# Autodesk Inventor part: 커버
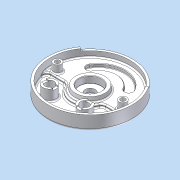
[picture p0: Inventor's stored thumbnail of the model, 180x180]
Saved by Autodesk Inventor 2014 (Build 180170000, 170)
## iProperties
Company: 한국ATC센터
Created: 2015-04
Part Number: 커버
Document SubType Name: Modeling
Designer: KYOUNG IL JANG
Density: 1 g/cm^3
Material: 일반
Mass: 394.015 g
Surface Area: 1019.6 cm^2
Volume: 394.015 cm^3
Appearance: 매끄러움 - 흰색
Author: KYOUNG IL JANG
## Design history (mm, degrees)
sketch "스케치1"
  geometry: L1 (-59, -19)-(-59, 19); L2 (59, 19)-(59, -19); L3 (-41, 19)-(-41, -19); L4 (41, -19)-(41, 19); L5 (38.527, 33.023)-(55.442, 39.179); L6 (-38.527, 33.023)-(-55.442, 39.179); C1 r 90 at (0, 0); C2 r 95 at (0, 0); A1 r 59 centre (0, 19) between (59, 19) and (-59, 19); A2 r 59 centre (0, -19) between (-59, -19) and (59, -19); A3 r 41 centre (0, -19) between (-41, -19) and (41, -19); A4 r 41 centre (0, 19) between (41, 19) and (-41, 19); 2 further points
  constraints: 12 end point, 12 point on circle, 6 centre point, 4 tangent, 2 parallel, 2 point on line, 1 coincident, 1 horizontal alignment, 1 midpoint, 1 vertical, 1 vertical alignment, 3 other
  dimensions: "d2" = 180 diameter of C1; "d3" = 156 dimension on A2 A1; "d4" = 118 distance between parallel lines of L2 L1; "d5" = 18 distance between parallel lines of L2 L4; "d8" = 190 diameter of C2; "d120" = 140 deg angle of L6 L5; "d121" = 110 deg dimension on A1.centre point (0, 0) L5.end
extrude "돌출1" new body sketch "스케치1" distance "d6" = 14; taper "d7" = 0 deg
extrude "돌출2" join sketch "스케치1" distance "d9" = 13; taper "d10" = 0 deg
extrude "돌출3" cut sketch "스케치1" distance "d11" = 7; taper "d12" = 0 deg
sketch "스케치2"
  geometry: C1 r 11.5 at (0, 0); 1 further point
  constraints: 1 centre point, 1 coincident
  dimensions: "d13" = 23 diameter of C1
extrude "돌출4" cut sketch "스케치2" stored distance "d14" = 7; taper "d15" = 0 deg
fillet "모깎기1"
fillet "모깎기2"
sketch "스케치3"
  geometry: L1 (-73.724, 51.622)-(-77.819, 54.49); L2 (73.724, 51.622)-(77.819, 54.49); L3 (0, 0)-(0, -90); A1 r 95 centre (0, 0) between (-77.819, 54.49) and (77.819, 54.49) reference; A2 r 90 centre (0, 0) between (-73.724, 51.622) and (73.724, 51.622) reference; 1 further point
  constraints: 6 end point, 5 point on circle, 1 point on line, 1 vertical, 1 other
  dimensions: "d16" = 250 deg dimension on L2 L1
extrude "돌출5" join sketch "스케치3" distance "d17" = 5; taper "d18" = 0 deg
hole "구멍1" diameter "d21" = 50; stored, may be unused: countersink angle "d25" = 90 deg, drill point angle "d27" = 0 deg; dims "d19" = 10, "d20" = 10, "d22" = 6, "d23" = 4, "d24" = 2, "d26" = 5
fillet "모깎기3" dims "d28" = 0.3
fillet "모깎기5" dims "d30" = 3
sketch "스케치4"
  geometry: C1 r 35 at (0, 0); C2 r 25 at (0, 0); 1 further point
  constraints: 2 centre point, 1 coincident
  dimensions: "d32" = 70 diameter of C1 (derived); "d36" = 10 radial gap between concentric circles of C1 C2
extrude "돌출6" join sketch "스케치4" distance "d33" = 10; taper "d34" = 0 deg
feature "면 기울기2" dims angle "d37" = 10 deg
chamfer "모따기1" distance "d39" = 1; stored, may be unused: second distance "d40" = 2, angle "d41" = 45 deg
fillet "모깎기7" dims "d42" = 5
sketch "스케치5"
  geometry: L1 (-40.249, -12)-(-89.196, -12); L2 (40.249, -12)-(89.196, -12); A1 r 90 centre (0, 0) between (-89.196, -12) and (89.196, -12) reference; A2 r 42 centre (0, 0) between (-40.249, -12) and (40.249, -12); 1 further point
  constraints: 4 end point, 4 point on circle, 1 centre point, 1 collinear, 1 horizontal, 1 point on line
  dimensions: "d43" = 48 radial gap between concentric circles of A1 A2; "d44" = 12 distance from line of point (0, 0) L1
extrude "돌출7" cut sketch "스케치5" stored distance "d45" = 10; taper "d46" = 0 deg
fillet "모깎기8" dims "d47" = 10
chamfer "모따기2" distance "d49" = 1; stored, may be unused: second distance "d50" = 2, angle "d51" = 45 deg
sketch "스케치7"
  geometry: L1 (36.062, 36.062)-(50.912, 50.912); L2 (-36.062, 36.062)-(-50.912, 50.912); A1 r 72 centre (0, 0) between (50.912, 50.912) and (-50.912, 50.912); A2 r 51 centre (0, 0) between (36.062, 36.062) and (-36.062, 36.062); 1 further point
  constraints: 8 point on circle, 4 end point, 2 centre point, 2 point on line, 1 coincident, 1 horizontal alignment
  dimensions: "d54" = 72 radius of A1; "d55" = 21 radial gap between concentric circles of A1 A2; "d56" = 90 deg angle of L2 L1
extrude "돌출8" join sketch "스케치7" distance "d57" = 5; taper "d58" = 0 deg
fillet "모깎기10" dims "d59" = 5
fillet "모깎기11" dims "d60" = 5
fillet "모깎기12" dims "d61" = 3
sketch "스케치6"
  geometry: C1 r 68 at (0, 0); 1 further point
  constraints: 1 centre point, 1 other
  dimensions: "d119" = 136 diameter of C1
feature "엠보싱1" sketch "스케치6" dims "d62" = 0.5, "d63" = 0
sketch "스케치8"
  geometry: C1 r 9 at (74, 0); C2 r 9 at (-74, 0); A1 r 74 centre (0, 0) between (74, 0) and (-74, 0); 1 further point
  constraints: 3 centre point, 2 horizontal alignment, 2 point on circle, 1 coincident, 1 equal radius
  dimensions: "d64" = 18 diameter of C1; "d65" = 148 diameter of A1
extrude "돌출9" join sketch "스케치8" stored distance "d66" = 5; taper "d67" = 0 deg
sketch "스케치11"
  geometry: C1 r 15 at (40, -52); C2 r 15 at (-40, -52); 1 further point
  constraints: 2 centre point, 1 equal radius, 1 horizontal alignment
  dimensions: "d83" = 52 vertical distance of point (0, 0) C1.centre; "d84" = 80 distance of C2.centre C1.centre; "d85" = 40 horizontal distance of point (0, 0) C1.centre (= 0.5 x d84); "d86" = 30 diameter of C1
extrude "돌출10" join sketch "스케치11" stored distance "d87" = 5; taper "d88" = 0 deg
node "구멍3"
node "구멍5"
hole "구멍6" diameter "d93" = 20; stored, may be unused: countersink angle "d97" = 90 deg, drill point angle "d99" = 118 deg; dims "d91" = 10, "d92" = 10, "d94" = 6, "d95" = 4, "d96" = 2, "d98" = 8
hole "구멍7" diameter "d102" = 20; stored, may be unused: countersink angle "d106" = 90 deg, drill point angle "d108" = 118 deg; dims "d100" = 10, "d101" = 10, "d103" = 6, "d104" = 4, "d105" = 2, "d107" = 8
sketch "스케치13"
  geometry: L1 (6, -13.748)-(6, -8); L2 (6, 8)-(6, 13.748); L3 (-6, -13.748)-(-6, -8); L4 (-6, 8)-(-6, 13.748); L5 (-66.252, -6)-(-72, -6); L6 (-88, -6)-(-93.748, -6); L7 (-66.252, 6)-(-72, 6); L8 (-88, 6)-(-93.748, 6); A1 r 15 centre (0, 0) between (6, -13.748) and (6, 13.748) reference; A2 r 10 centre (0, 0) between (6, -8) and (6, 8) reference; A3 r 15 centre (-80, 0) between (-66.252, -6) and (-93.748, -6) reference; A4 r 10 centre (-80, 0) between (-72, -6) and (-88, -6) reference; 1 further point
  constraints: 16 end point, 16 point on circle, 4 equal length, 3 collinear, 2 point on line, 1 perpendicular, 1 vertical
  dimensions: "d109" = 12 distance between parallel lines of L3 L1; "d110" = 6 distance from line of A1.centre L1 (= 0.5 x d109); "d111" = 12 distance between parallel lines of L7 L5; "d112" = 6 distance from line of A3.centre L5 (= 0.5 x d111)
extrude "돌출12" cut sketch "스케치13" distance "d113" = 3; taper "d114" = 0 deg
fillet "모깎기13" dims "d115" = 3
fillet "모깎기14" dims "d116" = 1
node "솔리드1"
sketch "스케치9"
  geometry: 1 further point
hole "구멍2" sketch "스케치9" diameter "d68" = 11; stored, may be unused: countersink angle "d72" = 90 deg, drill point angle "d74" = 0 deg; dims "d69" = 6, "d70" = 18, "d71" = 11, "d73" = 8
sketch "스케치10"
  geometry: 1 further point
hole "구멍4" sketch "스케치10" diameter "d75" = 11; stored, may be unused: countersink angle "d79" = 90 deg, drill point angle "d81" = 0 deg; dims "d76" = 6, "d77" = 18, "d78" = 11, "d80" = 8
